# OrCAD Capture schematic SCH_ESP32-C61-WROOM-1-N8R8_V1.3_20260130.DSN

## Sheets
1 01_DesignBlock: title: ESP32-C61-WROOM-1-N8R8; rev: V1.3; note: <01_DesignBlock>
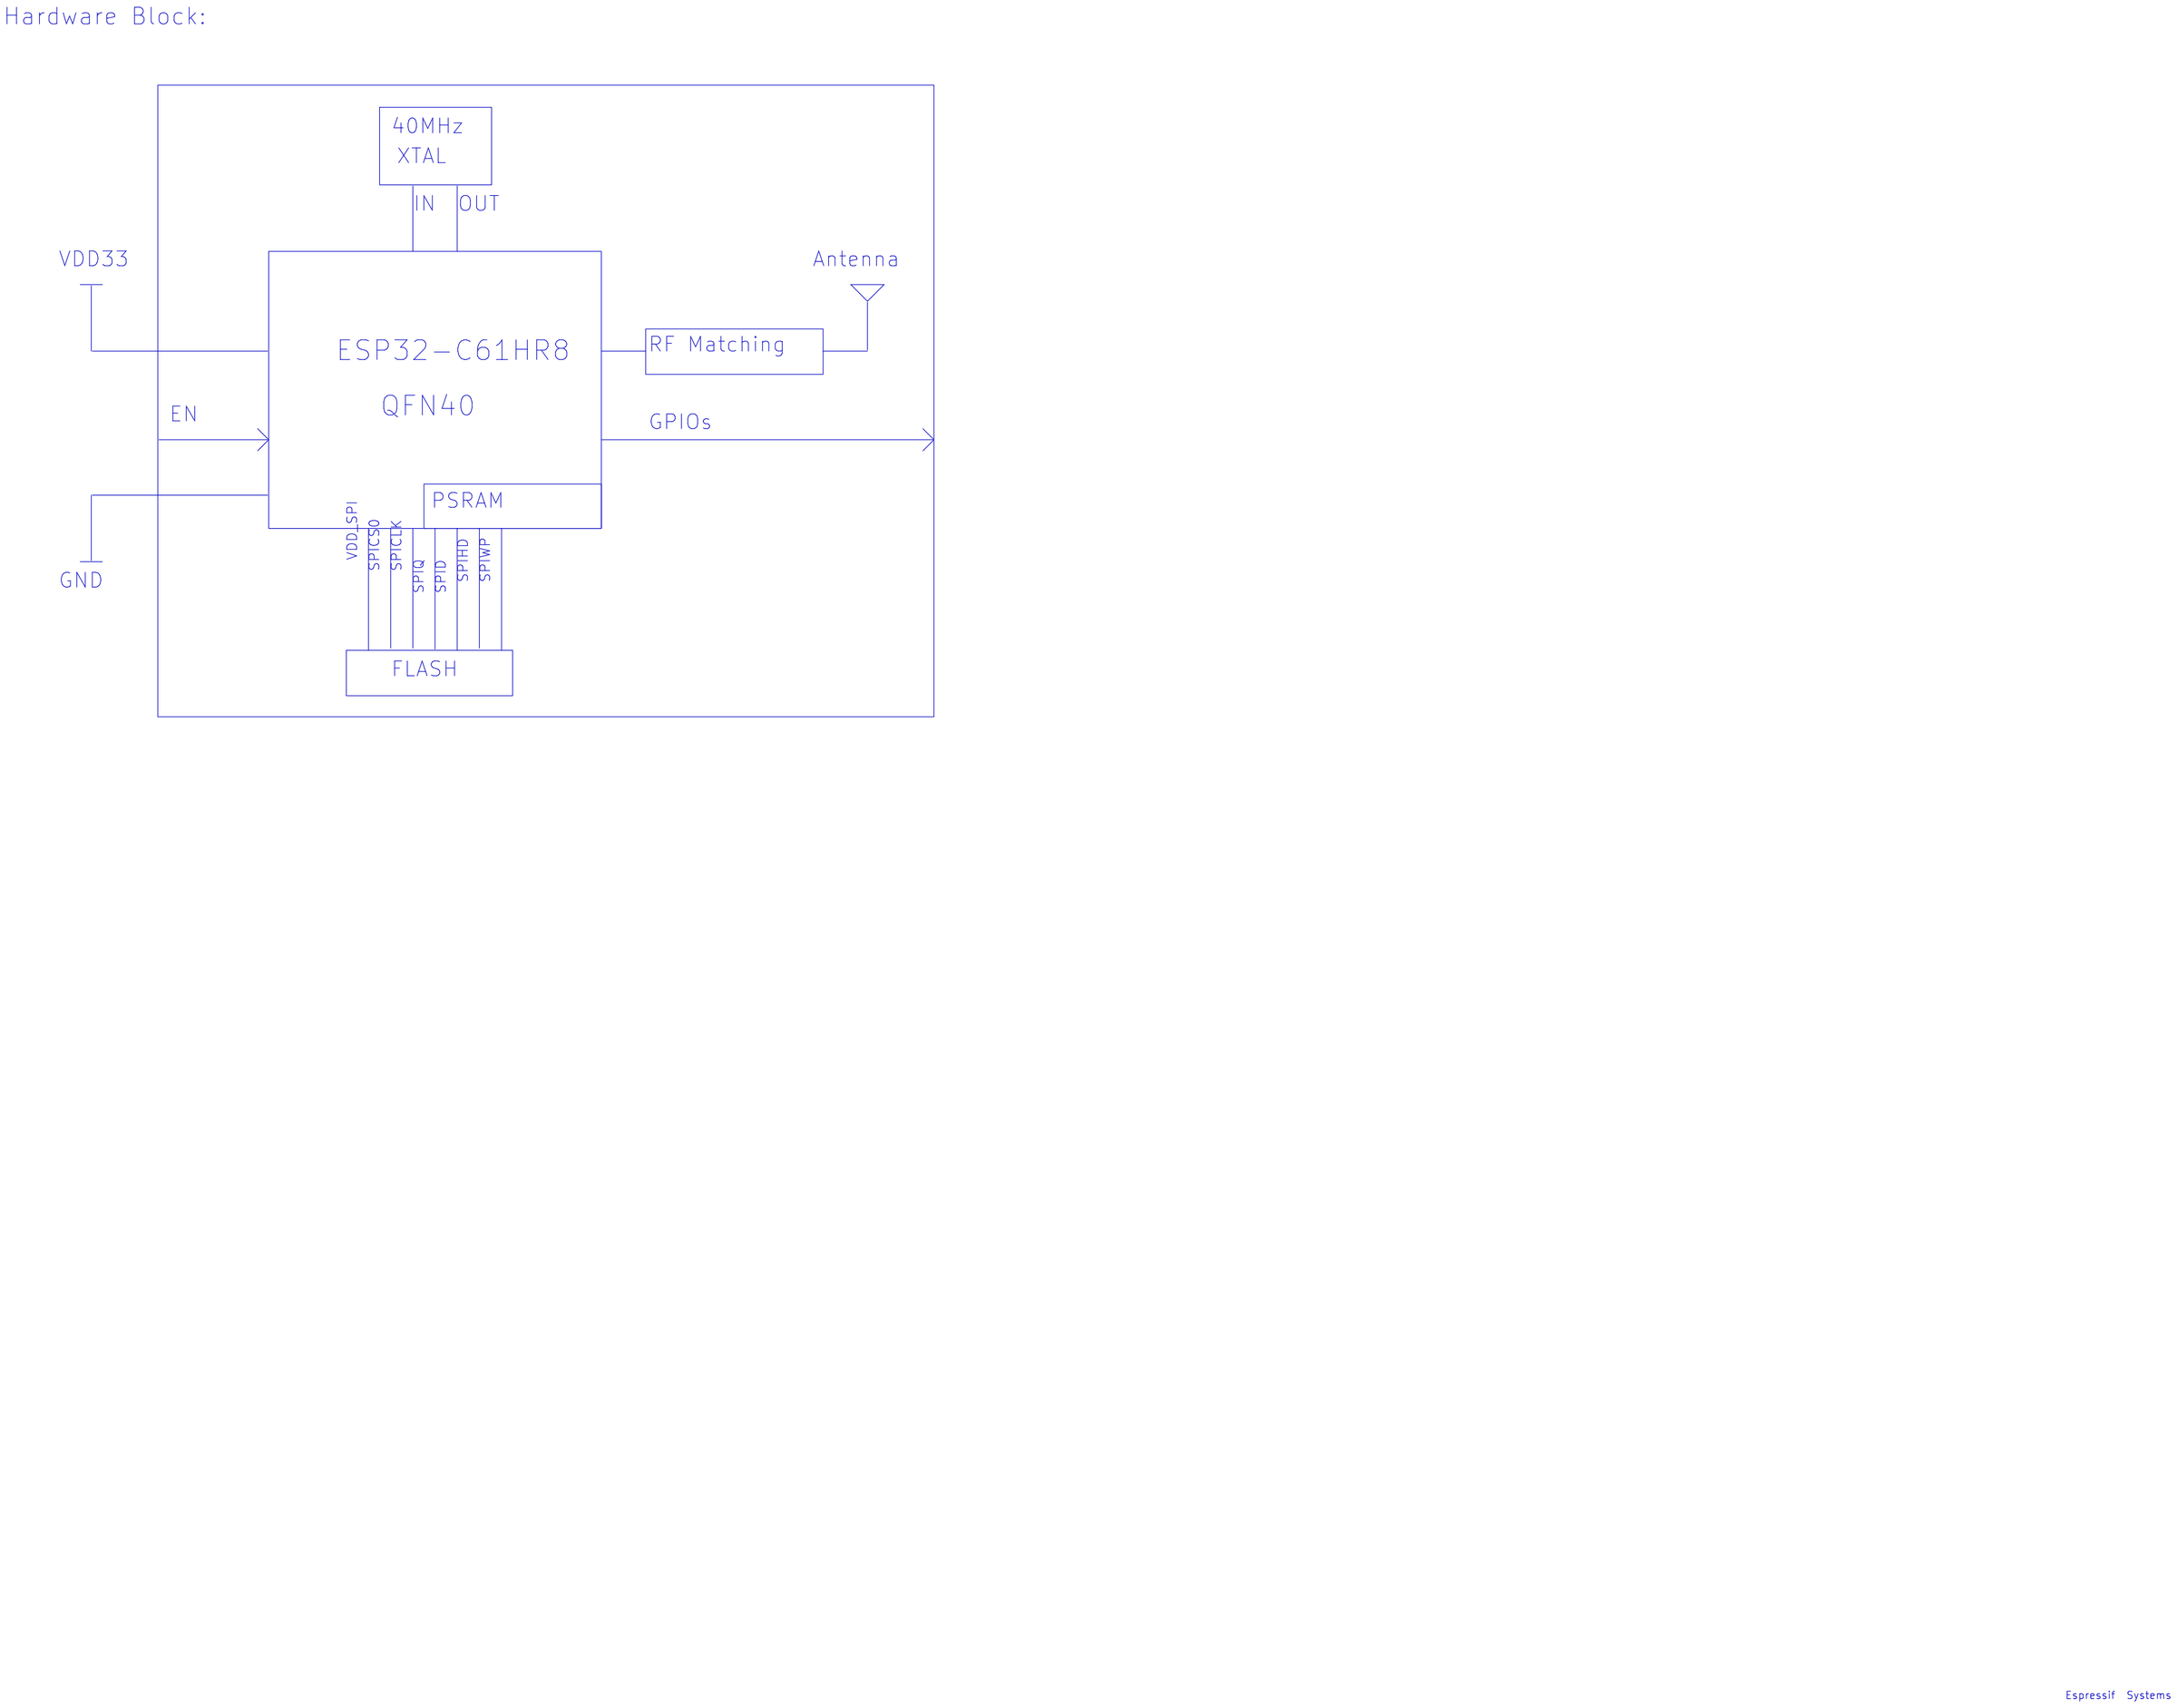
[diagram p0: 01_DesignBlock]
2 02_ESP32-C61-WROOM-1-N8R8: size A4; title: <ESP32-C611-WROOM-1-N8R8>; note: <02_ESP32-C61-WROOM-1-N8R8>
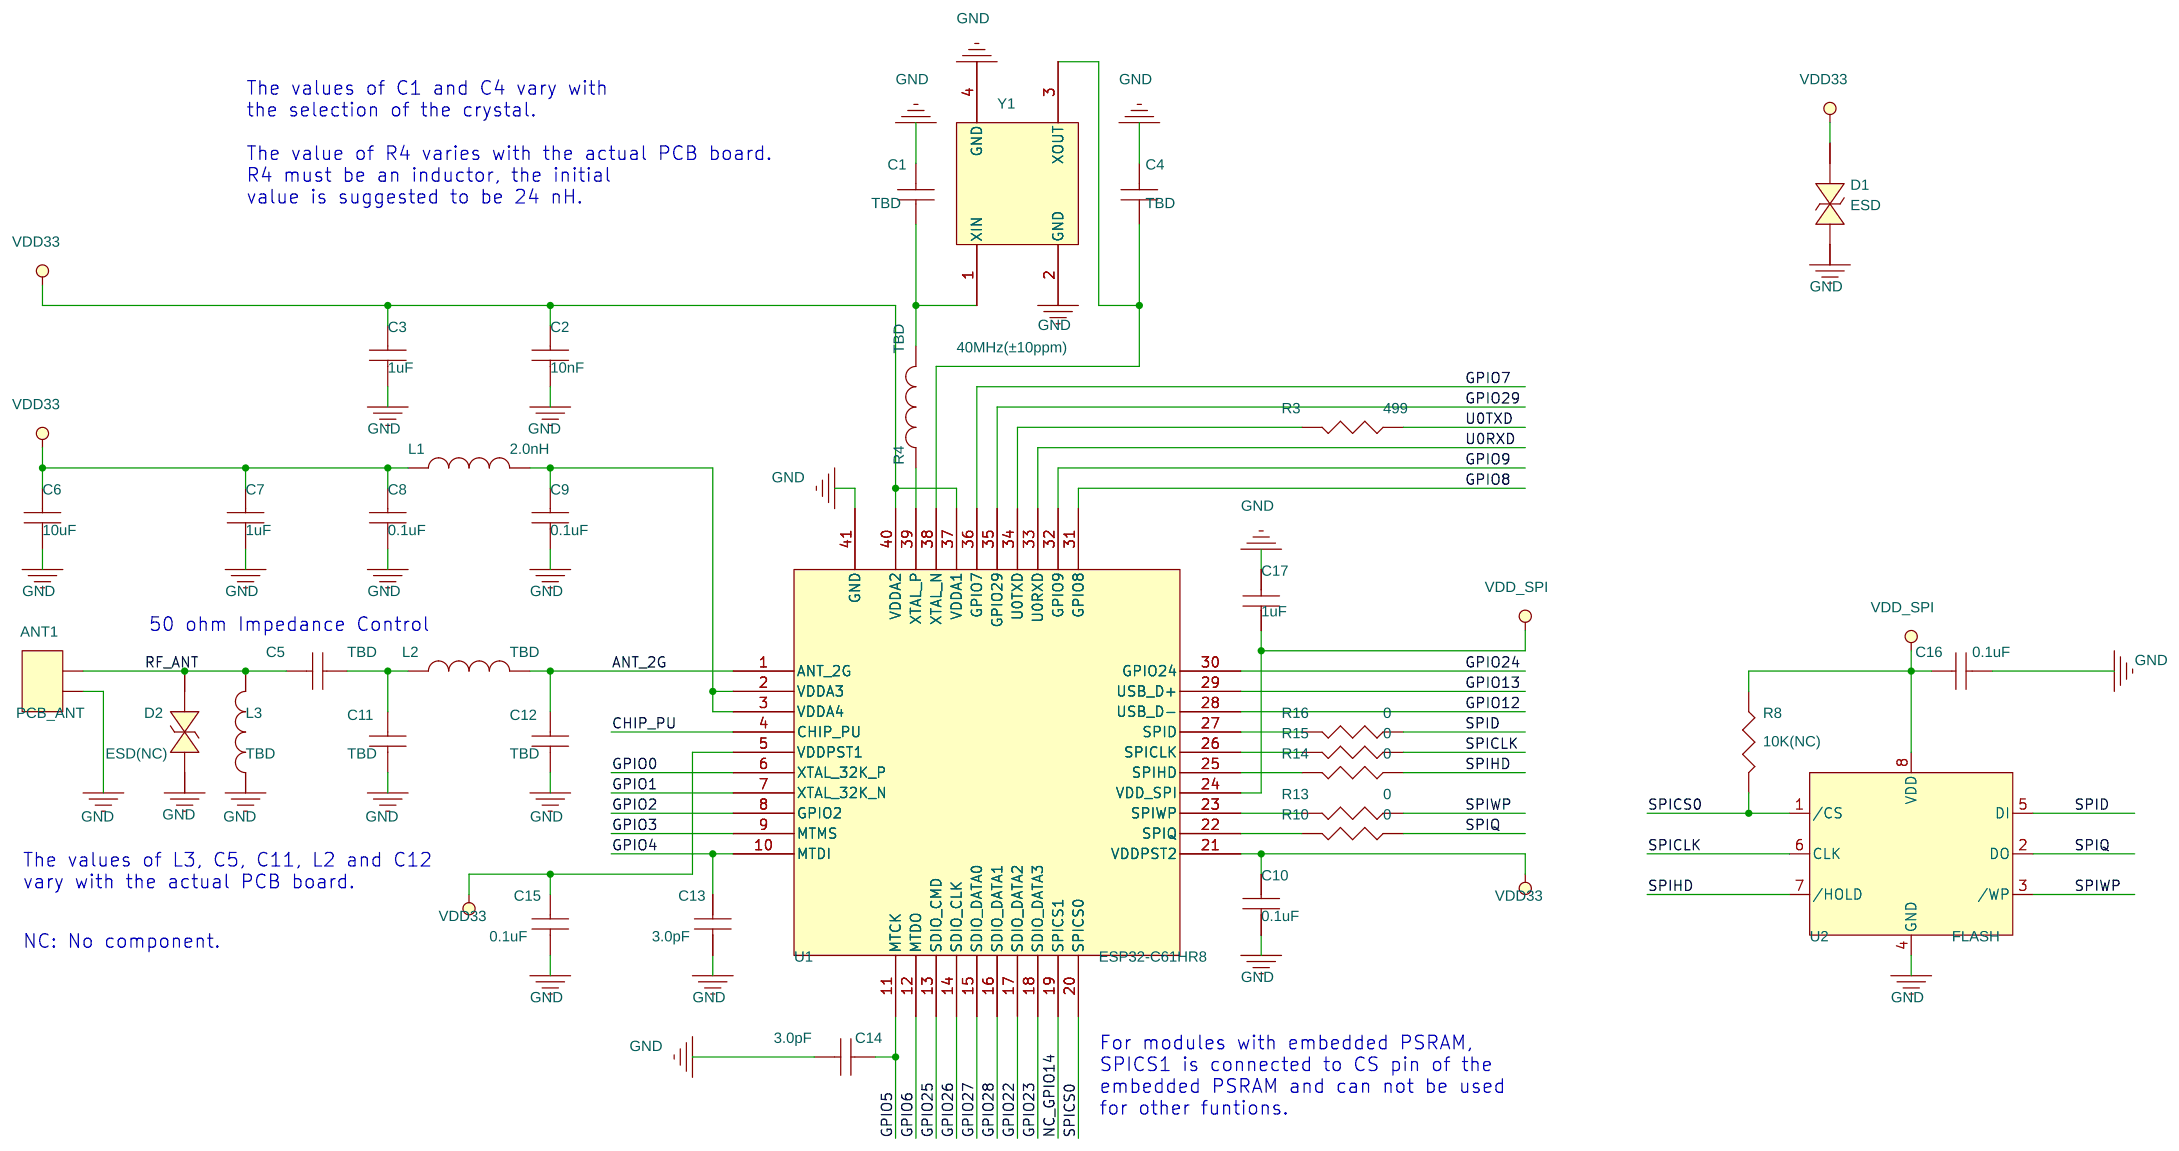
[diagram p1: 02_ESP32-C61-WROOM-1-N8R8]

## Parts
ANT1  PCB_ANT  [MINI-ANT-TYPEB]
C1  TBD  [C0201]
C2  10nF  [C0201]
C3  1uF  [C0201]
C4  TBD  [C0201]
C5  TBD  [C0201]
C6  10uF  [C0402]
C7  1uF  [C0201]
C8  0.1uF  [C0201]
C9  0.1uF  [C0201]
C10  0.1uF  [C0201]
C11  TBD  [C0201]
C12  TBD  [C0201]
C13  3.0pF  [C0201]
C14  3.0pF  [C0201]
C15  0.1uF  [C0201]
C16  0.1uF  [C0201]
C17  1uF  [C0201]
D1  ESD  [SOD882]
D2  ESD(NC)  [TSSLP-2-1]
L1  2.0nH  [L0201]
L2  TBD  [L0201]
L3  TBD  [L0201]
R3  499  [R0201]
R4  TBD  [R0201]
R8  10K(NC)  [R0201]
R10  0  [R0201]
R13  0  [R0201]
R14  0  [R0201]
R15  0  [R0201]
R16  0  [R0201]
U1  ESP32-C61HR8  [QFN40_0P4_5_E3P3]
U2  FLASH  [WSON8_1P27_8X6_E4P3X3P4]
Y1  40MHz(±10ppm)  [XTAL3225_2016]

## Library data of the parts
ANT1 = PCB_ANT
C1 C4 C5 C11 C12 = CAPACITOR
C2 = CAPACITOR: CODE12: ES01.1.1.103.3.6.2.00; Part Number: ES01111033620000; Part Type: Capacitor
C3 C7 C17 = CAPACITOR: CODE12: ES01.1.1.105.2.7.1.00; Part Number: ES01111052710000; Part Type: Capacitor
C6 = CAPACITOR: CODE12: ES01.1.2.106.2.7.1.00; Part Number: ES01121062710000; Part Type: Capacitor
C8-C10 C15 C16 = CAPACITOR: CODE12: ES01.1.1.104.2.6.1.00; Part Number: ES01111042610000; Part Type: Capacitor
C13 C14 = CAPACITOR: CODE12: ES01.1.1.3R0.6.2.2.00; Part Number: ES01113R06220000; Part Type: Capacitor
D1 = DIODE_BI_DIR: CODE12: ES06.1.1.3.01.00000; Part Number: ES06113010000000; Part Type: Diode
D2 = DIODE_BI_DIR: Options: ESD
L1 = INDUCTOR: CODE12: ES02.1.1.2N0.0.2.001; Part Number: ES02112N00200100; Part Type: Inductor
L2 L3 R4 = INDUCTOR
R3 = RESISTOR: CODE12: ES03.1.1.4990.1.000; Part Number: ES03114990100002; Part Type: Resistor
R8 = RESISTOR: CODE12: ES03.1.1.1002.1.000; Part Number: ES03111002100002; Part Type: Resistor
R10 R13-R16 = RESISTOR: CODE12: ES03.1.1.0000.1.000; Part Number: ES03110000100002; Part Type: Resistor
U1 = ESP32-C61-QFN40: CODE12: ES00.11.D.N.N.N.2.000; Part Number: ES0011DNNN200000; Part Type: ESP ICs
U2 = FLASH: CODE12: ES05.0.1.02.3.4.1.000; Part Number: ES05010234100001; Part Type: Memory ICs
Y1 = XTAL_4P: CODE12: ES04.1.4.4002.0.2.01; Part Number: ES04144002020100; Part Type: Clock

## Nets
GND: ANT1.2 C1.2 C2.2 C3.2 C4.2 C6.2 C7.2 C8.2 C9.2 C10.2 C11.2 C12.2 C13.2 C14.2 C15.2 C16.2 C17.2 D1.2 D2.2 L3.2 U1.41(GND) U2.4(GND) Y1.2(GND) Y1.4(GND)
VDD33: C2.1 C3.1 C6.1 C7.1 C8.1 C10.1 C15.1 D1.1 L1.2 U1.5(VDDPST1) U1.21(VDDPST2) U1.37(VDDA1) U1.40(VDDA2)
VDD_SPI: C16.1 C17.1 R8.1 U1.24(VDD_SPI) U2.8(VDD)
ANT_2G: C12.1 L2.1 U1.1(ANT_2G)
CHIP_PU: U1.4(CHIP_PU)
GPIO0: U1.6(XTAL_32K_P)
GPIO1: U1.7(XTAL_32K_N)
GPIO2: U1.8(GPIO2)
GPIO3: U1.9(MTMS)
GPIO4: C13.1 U1.10(MTDI)
GPIO5: C14.1 U1.11(MTCK)
GPIO6: U1.12(MTDO)
GPIO7: U1.36(GPIO7)
GPIO8: U1.31(GPIO8)
GPIO9: U1.32(GPIO9)
GPIO12: U1.28(USB_D-)
GPIO13: U1.29(USB_D+)
GPIO22: U1.17(SDIO_DATA2)
GPIO23: U1.18(SDIO_DATA3)
GPIO24: U1.30(GPIO24)
GPIO25: U1.13(SDIO_CMD)
GPIO26: U1.14(SDIO_CLK)
GPIO27: U1.15(SDIO_DATA0)
GPIO28: U1.16(SDIO_DATA1)
GPIO29: U1.35(GPIO29)
NC_GPIO14: U1.19(SPICS1)
RF_ANT: ANT1.1 C5.2 D2.1 L3.1
SPICLK: R15.2 U2.6(CLK)
SPICS0: R8.2 U1.20(SPICS0) U2.1(/CS)
SPID: R16.2 U2.5(DI)
SPIHD: R14.2 U2.7(/HOLD)
SPIQ: R10.2 U2.2(DO)
SPIWP: R13.2 U2.3(/WP)
U0RXD: U1.33(U0RXD)
U0TXD: R3.2
N16981224: C9.1 L1.1 U1.2(VDDA3) U1.3(VDDA4)
N16989795: C4.1 U1.38(XTAL_N) Y1.3(XOUT)
N16989829: C1.1 R4.1 Y1.1(XIN)
N17091728: R4.2 U1.39(XTAL_P)
N17141414: R3.1 U1.34(U0TXD)
N17179042: R14.1 U1.25(SPIHD)
N17179047: R15.1 U1.26(SPICLK)
N17179052: R16.1 U1.27(SPID)
N17179528: R10.1 U1.22(SPIQ)
N17179533: R13.1 U1.23(SPIWP)
N17185908: C5.1 C11.1 L2.2

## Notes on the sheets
sheet 1
- Hardware Block:
- 40MHz
- XTAL
- IN
- OUT
- VDD33
- Antenna
- ESP32-C61HR8
- RF Matching
- QFN40
- EN
- GPIOs
- PSRAM
- VDD_SPI
- GND
- SPICS0
- SPICLK
- SPIHD
- SPIWP
- SPIQ
- SPID
- FLASH
- Espressif  Systems
sheet 2
- The values of C1 and C4 vary with
  the selection of the crystal.
  The value of R4 varies with the actual PCB board.
  R4 must be an inductor, the initial
  value is suggested to be 24 nH.
- 50 ohm Impedance Control
- The values of L3, C5, C11, L2 and C12
  vary with the actual PCB board.
- NC: No component.
- For modules with embedded PSRAM,
  SPICS1 is connected to CS pin of the
  embedded PSRAM and can not be used
  for other funtions.
